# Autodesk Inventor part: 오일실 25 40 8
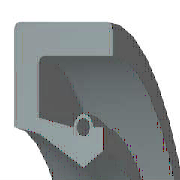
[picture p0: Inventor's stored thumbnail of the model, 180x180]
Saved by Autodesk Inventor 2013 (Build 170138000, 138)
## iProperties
IsCustomPart: 1
Created: 2009-02
Part Number: 오일실 25 40 8
Material: 고무
Description: 오일-실
Document SubType Name: Modeling
Standard: KS B 2804
Designer: 진현석
Standards Organization: KS
Language: ko-KR
Size Designation: S - 25 40 8
Categories: <MemberInstance><Categories><Category DisplayName="샤프트 부품" InternalName="7f7aeb1f-a693-4053-b835-cee3144e0d98" Mnemonic="SHFT"><Category DisplayName="실링" Intern
Density: 0.93 g/cm^3
Author: 진현석
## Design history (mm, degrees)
revolve "본체" stored, may be unused: angle "d17" = 90 deg
revolve "스프링1" stored, may be unused: angle "d18" = 90 deg
body "Solid1"
sketch "스케치1"
  geometry: L1 (0, 20)-(8, 20); L2 (8, 20)-(8, 18.75); L3 (8, 18.75)-(1.75, 18.75); L4 (0, 20)-(0, 14.6); L5 (0, 14.6)-(1.75, 14.25); L6 (1.75, 14.25)-(4.9, 12.5); L7 (4.9, 12.5)-(0, 12.5); L8 (6.3, 13.375)-(6.3, 14.6); L9 (0, 0)-(9.586, 0) reference; L10 (4.9, 12.5)-(6.3, 13.375); L11 (0, 18)-(0, -3) reference; L12 (-1.917, 0)-(11.503, 0) reference; L13 (4.2, 14.6)-(1.75, 15.09); L14 (1.75, 15.09)-(1.75, 18.75); L15 (6.3, 14.6)-(5.6, 14.6); C1 r 0.455 at (4.9, 14.6); A1 r 0.7 centre (4.9, 14.6) between (5.6, 14.6) and (4.2, 14.6)
  constraints: 26 end point, 5 horizontal alignment, 4 perpendicular, 2 centre point, 2 collinear, 2 horizontal, 2 parallel, 2 point on circle, 2 point on line, 2 vertical alignment, 1 coincident
  dimensions: "d0" = 40 diameter of L1 L9 (= SD2); "d1" = 26.75 diameter of L8.start L9 (= ABDM); "d2" = 1.25 distance of L1.end L2.end (computed from SD); "d3" = 0.91 diameter of C1 (= SPDI); "d4" = 1.4 diameter of A1 (= SPDA); "d5" = 25 diameter of L6.end L9 (= NND); "d6" = 28.5 diameter of L5.end L9 (= TKDM); "d7" = 29.2 diameter of L4.end L9 (= HLDM); "d8" = 4.9 distance from line of C1.centre L4 (= SPDST); "d9" = 6.3 distance between parallel lines of L8 L4 (= SDI); "d10" = 8 distance between parallel lines of L2 L4 (= SWDT); "d12" = 1.75 distance between parallel lines of L14 L4 (= SD)
fillet "모깎기1" dims "d11" = 0.3 (= RR)
other parameters: "SD2" = 40 [user parameter; used in 1 equation term], "SWDT" = 8 [user parameter; used in 1 equation term], "RR" = 0.3 [user parameter; used in 1 equation term], "SD" = 1.75 [user parameter; used in 2 equation terms], "NND" = 25 [user parameter; used in 1 equation term], "SPDA" = 1.4 [user parameter; used in 1 equation term], "SPDI" = 0.91 [user parameter; used in 1 equation term], "TKDM" = 28.5 [user parameter; used in 1 equation term], "HLDM" = 29.2 [user parameter; used in 1 equation term], "ABDM" = 26.75 [user parameter; used in 1 equation term], "SDI" = 6.3 [user parameter; used in 1 equation term], "SPDST" = 4.9 [user parameter; used in 1 equation term], "d13" = 0, "d14" = 0, "d15" = 0, "LAB" = 0.35 [user parameter]
